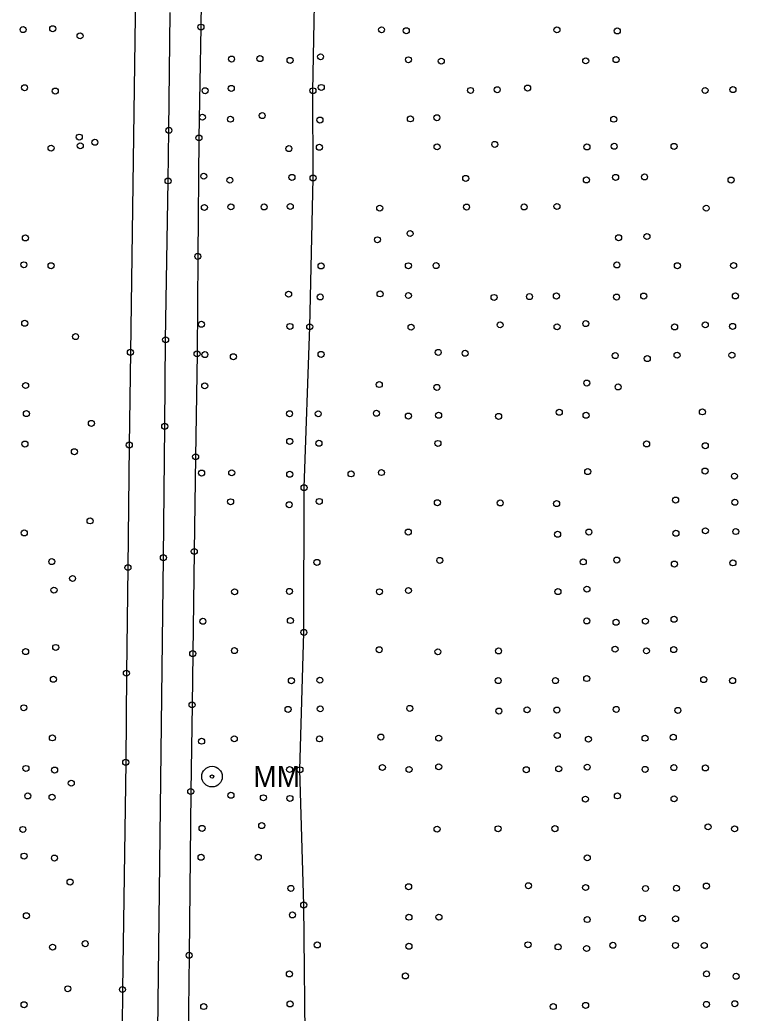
# Model space of a CAD drawing. Extents: x 20503438 to 20508873, y 7964251 to 7984667.
# Drawn here: x 20506637 to 20506876.4, y 7967040.5 to 7967371.4 of the extents above; entities that cross this region are included whole.
import ezdxf

# ---------------------------------------------------------------- set-up
doc = ezdxf.new("R2010")
doc.units = 0
for name, color, linetype in [('SurBreakLine', 7, 'Continuous'), ('SurConcreteSlab', 7, 'Continuous'), ('SurDrainageArrowUp', 7, 'Continuous'), ('SurEdgeRoadPaved', 7, 'Continuous'), ('SurRoadPoints', 7, 'Continuous'), ('SurSurveyPoints', 7, 'Continuous')]:
    doc.layers.add(name, color=color, linetype=linetype)

msp = doc.modelspace()

# ---------------------------------------------------------------- linework, layer by layer
at = {"layer": 'SurBreakLine'}
msp.add_lwpolyline([(20506676.27, 7967436.58), (20506673.75, 7967260.63), (20506673.38, 7967229.74), (20506672.93, 7967188.92), (20506672.41, 7967153.72), (20506672.19, 7967124.04), (20506671.1, 7967048.34), (20506670.26, 7966945.33), (20506669.67, 7966906.46), (20506669.41, 7966871.04), (20506668.85, 7966836.8), (20506668.54, 7966801.73), (20506668.02, 7966767.22), (20506667.76, 7966729.81), (20506666.24, 7966623.69), (20506665.51, 7966587.93), (20506664.19, 7966486.04), (20506662.51, 7966335.32), (20506661.23, 7966248.03), (20506660.03, 7966157.63), (20506658.3, 7966009.76)], dxfattribs=at)
at = {"layer": 'SurConcreteSlab'}
msp.add_lwpolyline([(20506697.65, 7967402.61), (20506697.25, 7967368.96), (20506696.56, 7967332.07), (20506696.19, 7967292.57), (20506695.95, 7967260.1), (20506695.47, 7967225.81), (20506695, 7967194.27), (20506694.51, 7967160.25), (20506694.26, 7967143.18), (20506693.83, 7967114.32), (20506693.31, 7967059.76), (20506692.61, 7967005.11), (20506692.38, 7966963.21), (20506691.98, 7966926.64), (20506691.36, 7966881.21), (20506690.92, 7966852.82), (20506690.63, 7966815.29), (20506689.98, 7966766.42), (20506689.74, 7966749.44), (20506689.7, 7966746.61), (20506689.28, 7966704.08)], dxfattribs=at)
at = {"layer": 'SurDrainageArrowUp'}
msp.add_lwpolyline([(20506725.56, 7966682.41), (20506728.02, 7966733.71), (20506727.82, 7966756.1), (20506729.96, 7966778.17), (20506730.53, 7966829.65), (20506730.14, 7966879.31), (20506729.13, 7966925.42), (20506730.94, 7966976.24), (20506732.01, 7967022.84), (20506731.44, 7967076.53), (20506730.2, 7967121.55), (20506731.5, 7967167.33), (20506731.55, 7967215.54), (20506733.45, 7967269.12), (20506734.55, 7967318.67), (20506734.51, 7967347.75), (20506735.53, 7967399.62)], dxfattribs=at)
at = {"layer": 'SurEdgeRoadPaved'}
msp.add_lwpolyline([(20506671.44, 7966131.99), (20506673.27, 7966261.84), (20506677.01, 7966570.96), (20506678.1, 7966642.03), (20506680.7, 7966833.13), (20506681.3, 7966886.9), (20506681.36, 7966892.52), (20506681.4, 7966895.33), (20506681.63, 7966918.21), (20506682.1, 7966969.83), (20506684.74, 7967192.21), (20506685.18, 7967235.97), (20506685.47, 7967264.79), (20506686.29, 7967317.73), (20506686.56, 7967334.59), (20506686.95, 7967373.78)], dxfattribs=at)
at = {"layer": 'SurRoadPoints'}
for radius in [3.43, 0.571]:
    msp.add_circle((20506700.92, 7967119.27), radius, dxfattribs=at)
at = {"layer": 'SurSurveyPoints'}
for centre in [(20506638.03, 7967368.12), (20506647.87, 7967368.43), (20506697.25, 7967368.96), (20506757.35, 7967368.06), (20506765.61, 7967367.77), (20506815.76, 7967368.04), (20506835.85, 7967367.67), (20506656.99, 7967366.04), (20506707.42, 7967358.31), (20506716.89, 7967358.45), (20506726.9, 7967357.86), (20506737.05, 7967359.06), (20506766.33, 7967358.07), (20506825.33, 7967357.72), (20506835.45, 7967358.12), (20506777.24, 7967357.62), (20506638.5, 7967348.76), (20506698.62, 7967347.76), (20506707.32, 7967348.53), (20506734.51, 7967347.75), (20506737.29, 7967348.86), (20506786.99, 7967347.86), (20506795.87, 7967348.1), (20506806, 7967348.66), (20506865.09, 7967347.85), (20506874.35, 7967348.14), (20506648.74, 7967347.66), (20506697.74, 7967338.95), (20506707.06, 7967338.27), (20506717.63, 7967339.46), (20506736.85, 7967337.98), (20506766.96, 7967338.38), (20506775.77, 7967338.78), (20506834.66, 7967338.27), (20506686.56, 7967334.59), (20506656.73, 7967332.31), (20506696.56, 7967332.07), (20506647.32, 7967328.64), (20506657.05, 7967329.41), (20506661.91, 7967330.58), (20506726.5, 7967328.49), (20506736.68, 7967328.93), (20506775.84, 7967329.06), (20506795.06, 7967329.89), (20506825.76, 7967329.04), (20506834.81, 7967329.24), (20506854.74, 7967329.23), (20506698.18, 7967319.29), (20506706.86, 7967317.96), (20506727.53, 7967318.89), (20506734.55, 7967318.67), (20506785.37, 7967318.56), (20506825.55, 7967318.04), (20506835.28, 7967318.88), (20506844.91, 7967319.05), (20506873.72, 7967318.01), (20506686.29, 7967317.73), (20506698.38, 7967308.87), (20506707.21, 7967309.07), (20506718.27, 7967309.04), (20506726.98, 7967309.2), (20506756.75, 7967308.65), (20506785.65, 7967309), (20506804.84, 7967309.06), (20506815.76, 7967309.2), (20506865.44, 7967308.64), (20506638.79, 7967298.72), (20506756.01, 7967298.11), (20506766.87, 7967300.19), (20506836.3, 7967298.79), (20506845.71, 7967299.19), (20506696.19, 7967292.57), (20506638.27, 7967289.78), (20506647.32, 7967289.48), (20506737.23, 7967289.4), (20506766.31, 7967289.45), (20506775.53, 7967289.51), (20506835.7, 7967289.74), (20506855.84, 7967289.46), (20506874.56, 7967289.53), (20506726.41, 7967279.98), (20506736.93, 7967279.05), (20506756.87, 7967280.08), (20506766.33, 7967279.54), (20506794.82, 7967278.9), (20506806.62, 7967279.18), (20506815.58, 7967279.38), (20506835.59, 7967279.02), (20506844.64, 7967279.37), (20506875.18, 7967279.41), (20506638.56, 7967270.29), (20506697.4, 7967269.95), (20506726.88, 7967269.24), (20506733.45, 7967269.12), (20506767.19, 7967268.99), (20506796.85, 7967269.77), (20506815.79, 7967269.11), (20506825.37, 7967270.19), (20506854.93, 7967269.06), (20506865.15, 7967269.77), (20506874.25, 7967269.27), (20506655.49, 7967265.84), (20506685.47, 7967264.79), (20506673.75, 7967260.63), (20506695.95, 7967260.1), (20506698.54, 7967259.85), (20506708.03, 7967259.15), (20506737.22, 7967259.93), (20506776.23, 7967260.59), (20506785.19, 7967260.3), (20506835.16, 7967259.51), (20506845.84, 7967258.53), (20506855.75, 7967259.66), (20506874.01, 7967259.67), (20506638.85, 7967249.56), (20506698.48, 7967249.44), (20506756.61, 7967249.88), (20506775.77, 7967248.94), (20506825.7, 7967250.37), (20506836.12, 7967249.09), (20506639.12, 7967240.21), (20506726.73, 7967240.16), (20506736.28, 7967240.14), (20506755.66, 7967240.3), (20506766.29, 7967239.38), (20506776.35, 7967239.64), (20506796.34, 7967239.28), (20506816.55, 7967240.65), (20506825.46, 7967239.64), (20506864.19, 7967240.77), (20506660.77, 7967236.93), (20506685.18, 7967235.97), (20506638.64, 7967230.06), (20506673.38, 7967229.74), (20506726.8, 7967230.94), (20506736.53, 7967230.32), (20506776.15, 7967230.26), (20506845.62, 7967230.1), (20506865.15, 7967229.49), (20506655.1, 7967227.49), (20506695.47, 7967225.81), (20506697.45, 7967220.4), (20506707.48, 7967220.48), (20506726.79, 7967219.99), (20506747.2, 7967220.12), (20506757.33, 7967220.56), (20506826, 7967220.87), (20506865.06, 7967221.06), (20506874.85, 7967219.37), (20506731.55, 7967215.54), (20506707.1, 7967210.83), (20506726.61, 7967209.84), (20506736.62, 7967210.94), (20506775.95, 7967210.53), (20506796.86, 7967210.45), (20506815.65, 7967210.21), (20506855.25, 7967211.4), (20506875, 7967210.67), (20506660.3, 7967204.46), (20506638.41, 7967200.46), (20506766.25, 7967200.74), (20506815.97, 7967199.99), (20506826.39, 7967200.73), (20506855.37, 7967200.34), (20506865.19, 7967201.15), (20506875.31, 7967200.91), (20506695, 7967194.27), (20506647.58, 7967190.91), (20506672.93, 7967188.92), (20506684.74, 7967192.21), (20506735.86, 7967190.63), (20506776.75, 7967191.32), (20506824.51, 7967190.8), (20506835.69, 7967191.42), (20506854.87, 7967190.07), (20506874.36, 7967190.47), (20506654.49, 7967185.28), (20506648.31, 7967181.39), (20506708.44, 7967180.83), (20506726.71, 7967180.98), (20506756.66, 7967180.85), (20506766.32, 7967181.26), (20506816.08, 7967180.9), (20506825.76, 7967181.72), (20506697.87, 7967171.02), (20506727.01, 7967171.26), (20506825.7, 7967171.14), (20506835.45, 7967170.67), (20506845.19, 7967171.07), (20506854.74, 7967171.68), (20506731.5, 7967167.33), (20506638.85, 7967160.9), (20506648.89, 7967162.3), (20506694.51, 7967160.25), (20506708.4, 7967161.23), (20506756.57, 7967161.54), (20506776.11, 7967160.85), (20506796.31, 7967161.15), (20506835.09, 7967161.72), (20506845.56, 7967161.16), (20506854.63, 7967161.57), (20506672.41, 7967153.72), (20506648.12, 7967151.68), (20506727.36, 7967151.21), (20506736.83, 7967151.4), (20506796.19, 7967151.25), (20506815.26, 7967151.26), (20506825.68, 7967151.94), (20506864.62, 7967151.58), (20506874.23, 7967151.26), (20506694.26, 7967143.18), (20506638.26, 7967142.2), (20506726.22, 7967141.68), (20506736.93, 7967141.85), (20506766.76, 7967142.01), (20506796.42, 7967141.11), (20506805.8, 7967141.53), (20506815.74, 7967141.45), (20506835.48, 7967141.66), (20506856.02, 7967141.35), (20506815.87, 7967132.98), (20506647.76, 7967132.17), (20506697.45, 7967131.06), (20506708.33, 7967131.86), (20506736.7, 7967131.84), (20506757.13, 7967132.44), (20506776.4, 7967132.09), (20506826.24, 7967131.74), (20506845.08, 7967132.06), (20506854.5, 7967132.39), (20506672.19, 7967124.04), (20506638.96, 7967121.99), (20506648.5, 7967121.46), (20506726.76, 7967121.64), (20506730.2, 7967121.55), (20506757.64, 7967122.31), (20506766.52, 7967121.65), (20506776.39, 7967122.54), (20506805.54, 7967121.56), (20506816.34, 7967121.87), (20506825.83, 7967122.42), (20506845.11, 7967121.69), (20506854.69, 7967122.27), (20506865.18, 7967122.17), (20506654.08, 7967117.08), (20506639.58, 7967112.82), (20506693.83, 7967114.32), (20506707.22, 7967113.04), (20506835.88, 7967112.85), (20506647.65, 7967112.41), (20506718.01, 7967112.22), (20506726.88, 7967112), (20506825.23, 7967111.77), (20506854.74, 7967111.87), (20506717.47, 7967102.94), (20506637.95, 7967101.67), (20506697.61, 7967102.04), (20506775.84, 7967101.77), (20506796.14, 7967101.89), (20506815.08, 7967101.93), (20506866.08, 7967102.53), (20506874.91, 7967101.87), (20506638.34, 7967092.79), (20506648.46, 7967092.13), (20506697.27, 7967092.4), (20506716.32, 7967092.43), (20506825.86, 7967092.21), (20506653.65, 7967084.14), (20506727.18, 7967082.04), (20506766.36, 7967082.6), (20506806.27, 7967082.93), (20506825.29, 7967082.32), (20506845.24, 7967081.99), (20506855.55, 7967082.09), (20506865.5, 7967082.8), (20506731.44, 7967076.53), (20506727.71, 7967073.18), (20506639.11, 7967072.92), (20506766.5, 7967072.43), (20506776.46, 7967072.45), (20506825.83, 7967071.65), (20506844.21, 7967072.09), (20506855.26, 7967071.9), (20506658.69, 7967063.62), (20506735.98, 7967063.2), (20506806.12, 7967063.25), (20506647.85, 7967062.46), (20506766.48, 7967062.76), (20506816.12, 7967062.55), (20506825.63, 7967062.01), (20506834.37, 7967063.08), (20506855.21, 7967063.03), (20506864.82, 7967063.02), (20506693.31, 7967059.76), (20506726.68, 7967053.54), (20506865.56, 7967053.55), (20506765.31, 7967052.86), (20506875.41, 7967052.76), (20506652.91, 7967048.59), (20506671.1, 7967048.34), (20506726.9, 7967043.53), (20506865.53, 7967043.4), (20506874.98, 7967043.63), (20506638.35, 7967043.28), (20506698.15, 7967042.67), (20506814.54, 7967042.67), (20506825.3, 7967043.07)]:
    msp.add_circle(centre, 1, dxfattribs=at)

# ---------------------------------------------------------------- texts
at = {"layer": 'SurRoadPoints'}
msp.add_text('MM', height=6.995, rotation=360, dxfattribs=at).set_placement((20506714.63, 7967115.77))

doc.saveas('drawing.dxf')
